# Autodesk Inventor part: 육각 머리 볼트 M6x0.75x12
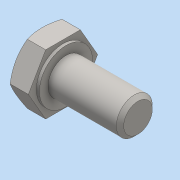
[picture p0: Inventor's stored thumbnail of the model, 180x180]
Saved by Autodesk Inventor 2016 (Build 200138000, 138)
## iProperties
Created: 2024-09
Part Number: 육각 머리 볼트 M6x0.75x12
Material: 일반
Description: 6각 머리 볼트 및 6각 머리 나사
Document SubType Name: Modeling
Designer: pc-7
Density: 1 g/cm^3
Appearance: 기본값
Author: jhkim
Sending System: Autodesk Inventor 2025
Preprocessor: ST-DEVELOPER v20
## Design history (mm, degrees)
node "육각 머리 볼트 M6x0.75x121"
node "솔리드1"
body "Solid1"
